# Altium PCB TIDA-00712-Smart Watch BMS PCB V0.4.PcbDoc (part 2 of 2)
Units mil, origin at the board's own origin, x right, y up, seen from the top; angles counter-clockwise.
Board outline 1150 x 800 mil, 2 copper layers (Top Layer, Bottom Layer), stack 11.461 mil thick; 83 components, 53 nets, 288 pads, 152 vias.
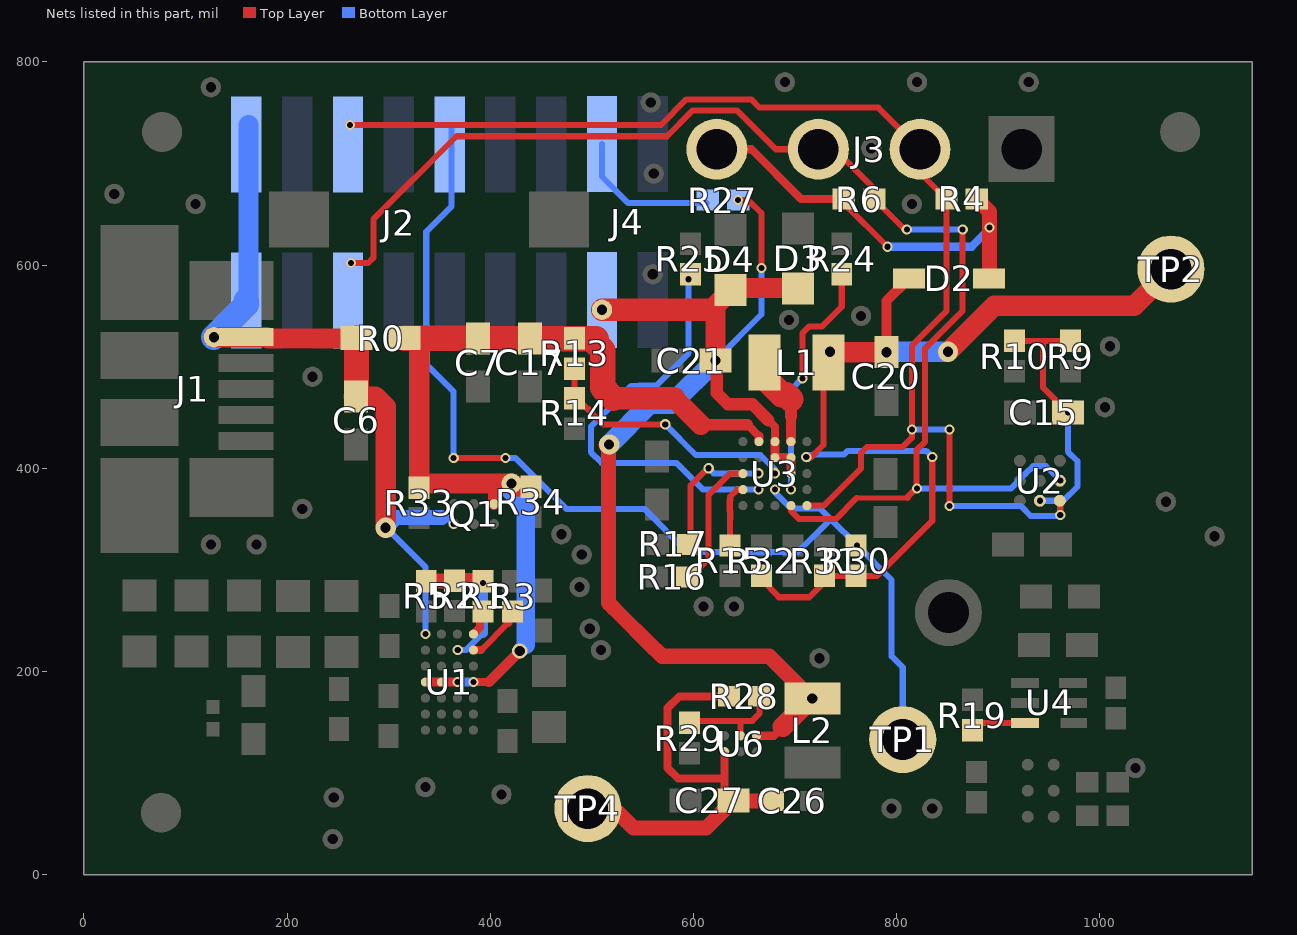
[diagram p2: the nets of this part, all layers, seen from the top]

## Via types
v1: diameter 10, hole 6, Top Layer to Bottom Layer, 77 vias
v2: diameter 20, hole 10, Top Layer to Bottom Layer, 61 vias
v3: diameter 10, hole 6, Top Layer to Bottom Layer, tented bottom, 4 vias
v4: diameter 30, hole 20, Top Layer to Bottom Layer, 4 vias
v5: diameter 16, hole 8, Top Layer to Bottom Layer, tented bottom, 3 vias
v6: diameter 60, hole 40, Top Layer to Bottom Layer, 2 vias
v7: diameter 15, hole 10, Top Layer to Bottom Layer, 1 vias

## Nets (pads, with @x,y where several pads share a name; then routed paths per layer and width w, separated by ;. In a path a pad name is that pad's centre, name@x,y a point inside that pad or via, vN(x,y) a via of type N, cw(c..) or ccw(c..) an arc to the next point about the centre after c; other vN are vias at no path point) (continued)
NetR1_1: R1.1 U1.G1 | length 25
  Top Layer w8: U1.G1@383.37,236.74 390,243.36 R1.1@390,259
NetR1_2: R1.2 R2.2 R5.2 U1.F2 | length 137.5
  Top Layer w6: R1.2@392.5,289.46 R1.2@393,288.96
  Top Layer w15: R5.2@337,288.96 364.26,288.96 R2.2@364.75,289.46 R1.2@392.5,289.46
  Bottom Layer w6: v1(368,221) 376,221 393,238
  Bottom Layer w10: 393,238 v1(393,287)
NetR3_2: R3.2 U1.F1 | length 56.2
  Top Layer w6: 391,221 417.75,247.75
  Top Layer w8: U1.F1@383.37,220.99 391,221 ; 417.75,247.75 R3.2@417.75,258.5
NetR13_1: R13.1 R14.2 U3.C3 | length 260.3
  Top Layer w6: R13.1@483,498.04 R14.2@483,468.96 484.04,470 495.98,458.06 496.55,458.06 501.24,453.38 501.24,452.8 510.79,443.25 v1(572.25,443.25)
  Bottom Layer w6: v1(572.25,443.25) 602.5,413 666,413 680,399 v1(680,395)
NetR15_2: R15.2 U3.D1 | length 64
  Top Layer w6: R15.2@636,323.92 636,350.29 636.18,350.47 636.18,357.32 635.71,357.79 635.71,368.56 636.18,369.03 636.18,372.18 642.92,378.92 U3.D1@648.71,378.92
NetR16_2: R16.2 U3.C1 | length 130.7
  Top Layer w6: R16.2@597,293 615,311 615,374 635.67,394.67 U3.C1@648.71,394.67
NetR17_2: R17.2 U3.C2 | length 136.3
  Top Layer w6: R17.2@593.96,324 R17.2@594.96,325 597,327.04 597,382.92 614.08,400 v1(615,400)
  Bottom Layer w6: v1(615,400) 620,395 v1(664,395)
NetR19_2: R19.2 U4.6 | length 44.5
  Top Layer w6: R19.2@882.08,149.62 882.39,149.32 U4.6@926.46,149.32
NetR24_1: R24.1 U3.D4 | length 240.1
  Top Layer w6: v1(707.25,488.52) 707.25,532.87 713.94,539.56 726.56,539.56 746,559 R24.1@746,591.04
  Bottom Layer w6: v1(696,379) 696,477.27 v1(707.25,488.52)
NetR25_1: R25.1 U3.D2 | length 404.3
  Bottom Layer w6: v1(595,586) 595,512.84 563.41,481.25 546.7,481.25 546.46,481 539,481 499,441 499,415.9 509.54,405.36 583.08,405.36 609.44,379 v1(664,379)
NetR28_1: R28.1 R29.2 U6.B1 | length 104.5
  Top Layer w6: R29.2@596,151.41 646.47,151.41 ; U6.B1@646.47,136.74 646.47,151.41 ; R28.1@661.92,175.49 R28.1@661.92,176.41 ; R28.1@664.96,175.49 664.96,158.45 657.92,151.41 646.47,151.41
PMID: C21.2 D3.1 D4.1 J4.2 L2.1 pad.0@510,556 R27.1 U3.A3 U3.B3 U3.B4 U3.C4 U6.A1 | length 1213.8
  Top Layer w6: v1(643.96,664) 654,664 667,651 v1(667,597)
  Top Layer w8: U6.A1@662.22,136.74 679.25,136.74 688,145.49 ; 674,447 680.2,440.8 U3.A3@680.2,426.17
  Top Layer w9: U3.A3@680.2,426.17 U3.B3@680.2,410.42 U3.B4@695.95,410.42 U3.C4@695.95,394.67
  Top Layer w12: C21.2@623,504 623,474 634,463 658,463 674,447
  Top Layer w15: v2@516.5,422.86 516.5,267.5 521.54,262.46 521.54,262.18 562.22,221.5 562.5,221.5 569,215 674.5,215 L2.1@716,173.49 ; 617.53,556 D4.1@621.62,560.09
  Top Layer w20: v2@516.5,422.86 v2(517,423.36) ; v2(621.62,506) 621.62,560.09 639,577.47 702.53,577.47 D3.1@703,577 ; 688,145.49 L2.1@716,173.49
  Top Layer w22: pad.0@510,556 617.53,556
  Bottom Layer w6: v2(621.62,506) 667,551.38 v1(667,597)
  Bottom Layer w20: v2(517,423.36) 556.89,463.25 578.87,463.25 v2(621.62,506)
  other v2: 717,173.5
PMID-S: J4.1 R27.2 | length 145.8
  Bottom Layer w6: J4.1@510,719 510,687 536,661 R27.2@613.04,661
RESET: J2.9 R30.2 TP1.1 U3.D3 | length 1086.8
  Top Layer w6: v1(364,410) v1(415,410)
  Bottom Layer w6: J2.9@362,737.77 362,657.75 337.04,632.79 337.04,502.31 364,475.35 v1(364,410) ; v1(415,410) 425,410 475,360 551.48,360 594.05,317.43 702.43,317.43 735,350 ; v1(680.2,378.92) 680.2,376.41 696.39,360.22 724.78,360.22 735,350 ; TP1.1@806,133 806,204 795,215 795,290 v1(761,324) 735,350
SCL: J2.5 J3.2 R4.2 U2.A3 U3.E5 | length 1280.9
  Top Layer w6: v1(262,737.77) 567.77,737.77 593,763 657,763 665,755 782,755 J3.2@823,714 823,691.04 R4.2@849.04,665 849.04,554.69 815.35,521 815,521 v1(815,438) 815,430 806,421 771,421 765,415 765,400 728.17,363.17 U3.E5@711.7,363.17 ; v1(852,363) v1(852,438) ; U2.A3@960.68,368 961,368.32 v1(961,354)
  Bottom Layer w6: v1(815,438) v1(852,438) ; v1(852,363) 922,363 932,353 960,353 v1(961,354)
SDA: J2.6 J3.3 R6.2 U2.A2 U3.E4 | length 1321.9
  Top Layer w5: 760.75,370.75 810.75,370.75
  Top Layer w6: v1(263,602) 279.77,602 285,607.23 285,645 366.77,726.77 574,726.77 574,727 599,752 643,752 681,714 J3.3@723,714 ; U3.E4@695.95,363.17 695.95,358.05 704,350 740,350 760.75,370.75 ; J3.3@723,730 777.96,675.04 R6.2@777.96,665 807.96,635 v1(810,635) ; 810.75,370.75 811.25,371.25 ; 810.75,371.75 819.5,380.5 819.5,417.5 828,426 828,518 865,555 v1(865,635)
  Bottom Layer w6: v1(810,635) v1(865,635) ; v1(820,380) 912.09,380 926.46,394.37 926.7,394.37 934.32,401.99 934.32,402.23 946.77,402.23 v1(961,388)
SW: L1.1 U3.A4 | length 91.4
  Top Layer w10: U3.A4@695.95,426.17 695.95,451.05
  Top Layer w12: L1.1@670.01,493.94 L1.1@670.01,504 ; 695.95,451.05 695.95,468
  Top Layer w25: L1.1@670.01,493.94 673.5,490.45 673.5,485.68 686.68,472.5 691.45,472.5 695.95,468
USB_5V: C6.1 J1.1 J2.1 J2.2 pad.0@128,529 Q1.A1 R0.1 U1.G4 | length 766.9
  Top Layer w20: pad.0@128,529 179.76,529 181,527.76 268.13,527.76 R0.1@268.38,528 ; C6.1@268,470.62 286.88,470.62 297,460.5 v2(297,341.48)
  Top Layer w25: C6.1@268,470.62 268.38,471 R0.1@268.38,528
  Bottom Layer w6: v2@297.26,341.74 336.13,302.87 v1(336.13,236.74) ; 355,354 v1(364,345)
  Bottom Layer w15: v2@297.26,341.74 307.15,351.63 352.63,351.63
  Bottom Layer w20: J2.2@160,565 162,567 J2.1@162,737.77
  Bottom Layer w25: pad.0@128,529 160,561 J2.2@160,565
VBOOST: C26.1 C27.1 R28.2 TP4.1 U6.C2 | length 452.2
  Top Layer w6: C27.1@630.72,81.9 C27.1@639.62,73 ; C27.1@633.25,73.49 C27.1@633.72,73.97
  Top Layer w8: C27.1@630.72,81.9 630.72,94.49 ; U6.C2@630.72,120.99 630.72,94.49 ; R28.2@635.04,175.49 586,175.49 574.43,163.92 574.43,105.07 585,94.49 630.72,94.49
  Top Layer w15: TP4.1@483,65 TP4.1@496,65 522,65 541,46 612.62,46 C27.1@639.12,72.49 ; C27.1@639.62,73 C27.1@639.12,72.49 ; C26.1@678.39,72.49 C26.1@677.32,72.49 C27.1@639.12,72.49
VDD: C15.1 R9.1 R10.1 U2.B3 | length 255.3
  Top Layer w6: R10.1@916,525.41 944,525.41 ; v1(968.62,455) 944,479.62 944,525.41 ; R9.1@971,525.41 944,525.41
  Bottom Layer w6: v1(941,368) 964,368 978,382 978,407 968.62,416.38 v1(968.62,455)
VDD_I2C: D2.1 J3.4 R4.1 R6.1 | length 416.4
  Top Layer w6: R6.1@748.04,660.93 v1(791,617.97)
  Top Layer w8: J3.4@623,714 657,714 706,665 R6.1@748.04,665 R6.1@748.04,660.93
  Top Layer w15: R4.1@878.96,665 891.49,652.47 v1(891.49,637) D2.1@891.49,590.4
  Bottom Layer w8: v1(791,617.97) 874.03,617.97 873.9,618.1 v1@892.49,636.69
  Bottom Layer w15: J3.4@609,729 J3.4@626,729
VIN: C7.1 C17.1 Q1.C2 R0.2 R13.2 R33.1 R34.1 U1.D1 U1.D2 U1.D3 U1.D4 U3.A2 | length 1023.2
  Top Layer w8: v3(383.37,189.5) 398.5,189.5 ; 653.08,442.9 664.46,431.53
  Top Layer w9: U1.D4@336.13,189.5 U1.D3@351.88,189.5 v3(367.62,189.5) ; U3.A2@664.46,426.17 664.46,431.53
  Top Layer w10: 398.5,189.5 v7(429,220)
  Top Layer w11: 607.1,442.9 653.08,442.9
  Top Layer w12: Q1.C2@403.68,364.84 403.68,379.68
  Top Layer w15: 333,528.62 C7.1@388,528.62
  Top Layer w20: R33.1@330,380.96 R33.1@330,385 ; 333,528.62 332.38,528 330,525.62 R33.1@330,385 ; v2(421,385) R33.1@330,385 ; v2@424.04,381.96 R34.1@440,381.96 ; 581.2,468.8 607.1,442.9
  Top Layer w22: 521.2,468.8 581.2,468.8
  Top Layer w25: R0.2@315.62,528 332.38,528 387.62,528 C7.1@388,527.62 504.38,527.62 504.38,522.67 510.74,516.31 510.74,479.26 521.2,468.8
  Bottom Layer w9: v3(367.62,189.5) v3(383.37,189.5)
  Bottom Layer w15: v7(429,220) 435,226
  Bottom Layer w18: 435,226 435,363.96
  Bottom Layer w20: v2(421,385) 421,377.96 435,363.96
VSYS: C20.1 D2.2 L1.2 R30.1 R31.1 R32.2 TP2.1 U3.B5 | length 939.1
  Top Layer w6: R32.2@667,294 667,290.6 684,273.6 684,273 714,273 729,288 R31.1@729,294 759.92,294 R30.1@760,294.08 780.83,294.08 835,348.25 v1(835,411) ; v1(711,411) 714.83,411 715.42,410.42 728,423 L1.2@728,489
  Top Layer w10: v2(790,514.24) 790,564.74 D2.2@812.26,587
  Top Layer w20: L1.2@743.24,514.24 v2(790,514.24) ; v2(850.62,514.62) 896,560 1034,560 TP2.1@1070,596
  Top Layer w25: L1.2@733,516 v2(734.38,514.62)
  Bottom Layer w6: v1(711,411) 711.12,411 712.12,410 715.28,413.17 717.09,413.17 717.59,413.67 748.34,413.67 751.68,417 829,417 v1(835,411)
  Bottom Layer w20: v2@790,514.62 v2(850.62,514.62)
pads on no net: FID1.1 FID2.1 FID3.1 J1.2 J1.3 J1.4 J1.6 J1.7 J1.8 J1.9 J1.10 J1.11 Q1.B1 Q1.B2 U1.F4 U4.1

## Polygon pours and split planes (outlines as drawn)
GND on Top Layer "Top Layer-No Net" (solid, remove dead copper, pour order 19): 0,800 1150,800 1150,0 0,0 0,800
GND on Bottom Layer "Top Layer-No Net" (solid, remove dead copper, pour order 23): 0,800 1150,800 1150,0 0,0 -2.09,2.09 -2.09,800

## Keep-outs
Keep-Out Layer:
  lines w5: 0,0 0,800 1150,800 1150,0 0,0
  lines w10: -5,3450 cw(c0,3450) 0,3455 ccw(c0,3450) -5,3450 ; 4950,3455 cw(c4950,3450) 4955,3450 ccw(c4950,3450) 4950,3455
  text ".Layer_Name" at 577,-858.49 h44

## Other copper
Top Layer:
  text ".Layer_Name" at 577,-858.49 h44
Bottom Layer:
  text ".Layer_Name" at 577,-858.49 h44

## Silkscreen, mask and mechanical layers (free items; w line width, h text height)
Top Overlay:
  text ".Layer_Name" at 577,-858.49 h40
Bottom Overlay:
  lines w4: 35.14,66 35.14,146 ; 75.14,92.67 35.14,106 ; 75.14,119.33 35.14,106 ; 214.27,106 35.14,106 ; 297,106 476.14,106 ; 376.53,117.99 456.53,117.99 ; 376.53,301.99 456.53,301.99 ; 403.2,157.99 416.53,117.99 ; 403.2,261.99 416.53,301.99 ; 416.53,167.94 416.53,117.99 ; 416.53,252.04 416.53,301.99 ; 429.86,157.99 416.53,117.99 ; 429.86,261.99 416.53,301.99 ; 436.14,92.67 476.14,106 ; 436.14,119.33 476.14,106 ; 476.14,66 476.14,146 ; 547.18,440 547.18,520 ; 562,280 642,280 ; 562,537 642,537 ; 587.18,466.67 547.18,480 ; 587.18,493.33 547.18,480 ; 588.67,320 602,280 ; 588.67,497 602,537 ; 589,91.67 589,99.67 ; 602,341.18 602,280 ; 602,475.82 602,537 ; 609.37,480 547.18,480 ; 615.33,320 602,280 ; 615.33,497 602,537 ; 629,82.33 589,95.67 ; 629,109 589,95.67 ; 640.4,95.67 589,95.67 ; 724.6,95.67 776,95.67 ; 736,82.33 776,95.67 ; 736,109 776,95.67 ; 744,480 806.18,480 ; 766.18,466.67 806.18,480 ; 766.18,493.33 806.18,480 ; 776,91.67 776,99.67 ; 806.18,440 806.18,520 ; 843,216 843,224 ; 883,206.67 843,220 ; 883,233.33 843,220 ; 885.38,220 843,220 ; 944.33,82.59 957.67,42.59 ; 944.33,198.59 957.67,238.59 ; 953.67,42.59 961.67,42.59 ; 953.67,238.59 961.67,238.59 ; 957.67,98.49 957.67,42.59 ; 957.67,182.69 957.67,238.59 ; 969.62,220 1012,220 ; 971,82.59 957.67,42.59 ; 971,198.59 957.67,238.59 ; 972,206.67 1012,220 ; 972,233.33 1012,220 ; 1012,216 1012,224
  lines w5: 35,119 35,303 476,303 476,119 35,119 ; 547,279.5 547,537 806,537 806,279.5 547,279.5 ; 589,69 589,211 777,211 777,69 589,69 ; 843,44 843,241 1012,241 1012,44 843,44 ; 902,359 902,470 987,470 987,359 902,359
  text "BQ25120" at 808.15,569.32 h40
  text "V0.3" at 43,514 h40 r270
  text "BQ27421" at 1045,476 h40
  text "259" at 619.37,456.01 h40
  text "TIDA-00712" at 382,438 h40
  text "257" at 625.99,351.18 h40 r90
  text "BQ51003" at 266,335 h40
  text "BQ29702" at 1133,285 h40
  text "Bster" at 712,220 h40
  text "169" at 895.38,201.92 h40
  text "184" at 434.61,177.94 h40 r90
  text "196" at 975.75,108.49 h40 r90
  text "441" at 224.27,88.14 h40
  text "187" at 650.4,77.59 h40
  text ".Layer_Name" at 577,-858.49 h44
Top Paste:
  text ".Layer_Name" at 577,-858.49 h44
Bottom Paste:
  text ".Layer_Name" at 577,-858.49 h44
Top Solder:
  text ".Layer_Name" at 577,-858.49 h44
  text ".Layer_Name" at 577,-858.49 h44
Bottom Solder:
  text ".Layer_Name" at 577,-858.49 h44
Drill Guide:
  text ".Layer_Name" at 577,-858.49 h44
M1 Board Outline:
  the board outline again, w5
  text ".Layer_Name" at 577,-858.49 h44
M2 Board Dimensions:
  rectangle: 0,-275 125,-150
  rectangle: 125,-400 500,-275
  lines w5: 0,0 0,800 1150,800 1150,0 0,0
  lines w7: 0,-275 1000,-275 ; 125,-400 125,-150 ; 250,-400 250,-150 ; 500,-400 500,-150 ; 750,-400 750,-150 ; 0,-400 1000,-400 1000,-150 0,-150 0,-400
  lines w10: -72.8,750.04 -56.83,800.27 ; -66.83,800.13 -46.83,800.41 ; -63.18,50.04 -45.83,0.27 ; -55.83,0.13 -35.83,0.41 ; -55.53,705.81 -56.83,800.27 ; -47.13,94.73 -45.83,0.27 ; -39.47,750.5 -56.83,800.27 ; -29.85,50.49 -45.83,0.27 ; -0.05,-53.1 -0.02,-33.1 ; 49.94,-59.86 -0.03,-43.1 ; 49.99,-26.52 -0.03,-43.1 ; 252.73,-43.54 -0.03,-43.1 ; 897.2,-44.66 1149.97,-45.1 ; 1099.94,-61.68 1149.97,-45.1 ; 1099.99,-28.35 1149.97,-45.1 ; 1149.95,-55.1 1149.98,-35.1
  text "800.076 (mil)" at -84.38,695.42 h50 r270.79
  text "1150.002 (mil)" at 262.68,-72.55 h50 r359.9
  text ".Layer_Name" at 577,-858.49 h44
M3 3D STEP Top:
  text ".Layer_Name" at 577,-858.49 h44
M4 3D STEP Bottom:
  text ".Layer_Name" at 577,-858.49 h44
M5 Assembly Top:
  lines w10: -292,-930.17 6308,-930.17 ; -292,-726.83 6310,-726.83 ; -292,-523.5 -292,-1133.5 3713,-1133.5 6310,-1133.5 6310,-523.5 -291.5,-523.5 -291.5,-1133.5 1284,-1133.5 ; 2173,-1133.5 2173,-523.5 ; 3440,-726.83 3440,-523.5 ; 4280,-726.83 4280,-523.5 ; 4902,-1140 4902,-937.17
  text "COMPONENTS MARKED 'DNP' SHOULD NOT BE POPULATED." at 1153.5,-318.5 h44
  text "ASSEMBLY VARIANT:" at 1153,-434 h44
  text ".VariantName" at 2189,-434 h44
  text "PCB VIEWED FROM TOP SIDE" at -228.5,-655.67 h44
  text "BOARD #:" at 2248,-655.67 h44
  text ".PRJ_Number" at 2793.5,-655.67 h44
  text "REV:" at 3638,-655.67 h44
  text ".PCB_Rev" at 3929.5,-655.67 h44
  text "SVN REV:" at 4476,-655.67 h44
  text ".VersionControl_RevNumber" at 4982,-655.67 h44
  text "TID #:" at 2248,-859 h44
  text ".TID" at 2793.5,-859 h44
  text "PLOT NAME =" at -228.5,-1064.34 h44
  text ".plot_File_Name" at 577,-1064.34 h44
  text "GENERATED    :" at 2250,-1064.34 h44
  text ".Print_Date" at 3119.5,-1064.34 h44
  text ".Print_Time" at 3848.5,-1064.34 h44
  text "TEXAS INSTRUMENTS" at 5113,-1064.34 h44
M6 Assembly Bottom:
  lines w10: -292.5,-727.33 6309.5,-727.33 ; -290.5,-930.67 6309.5,-930.67 ; 1115.5,-1140.5 1115.5,-937.67 ; 1737.5,-727.33 1737.5,-524 ; 2577.5,-727.33 2577.5,-524 ; 3844.5,-1134 3844.5,-524 ; 4733.5,-1134 6309,-1134 6309,-524 -292.5,-524 -292.5,-1134 2304.5,-1134 6309.5,-1134 6309.5,-524
  text "COMPONENTS MARKED 'DNP' SHOULD NOT BE POPULATED." at 6102,-318 h44
  text ".VariantName" at 5058,-434 h44
  text "ASSEMBLY VARIANT:" at 6097,-434 h44
  text ".VersionControl_RevNumber" at 1035.5,-656.17 h44
  text "SVN REV:" at 1541.5,-656.17 h44
  text ".PCB_Rev" at 2088,-656.17 h44
  text "REV:" at 2379.5,-656.17 h44
  text ".PRJ_Number" at 3224,-656.17 h44
  text "BOARD #:" at 3769.5,-656.17 h44
  text "PCB VIEWED FROM BOTTOM SIDE" at 6246,-656.17 h44
  text ".TID" at 3224,-859.5 h44
  text "TID #:" at 3769.5,-859.5 h44
  text "TEXAS INSTRUMENTS" at 904.5,-1064.84 h44
  text ".Print_Time" at 2169,-1064.84 h44
  text ".Print_Date" at 2898,-1064.84 h44
  text "GENERATED    :" at 3767.5,-1064.84 h44
  text ".plot_File_Name" at 5440.5,-1064.84 h44
  text "PLOT NAME =" at 6246,-1064.84 h44
M9 Title Sheet:
  drawing of 57 lines, arcs and shapes, not listed
  text "1" at 739.84,8036.5 h44
  text "2" at 3235.5,8036.5 h44
  text "3" at 5724.84,8036.5 h44
  text "4" at 8231.51,8036.5 h44
  text "5" at 10730.5,8036.5 h44
  text "6" at 13235.5,8036.5 h44
  text "A" at -416.5,6893.5 h44
  text "A" at 14383.5,6893.5 h44
  text "B" at -416.5,4513.5 h44
  text "B" at 14383.5,4513.5 h44
  text "C" at -416.5,2138.5 h44
  text "C" at 14383.5,2138.5 h44
  text "PROJECT TITLE:" at 11343.5,277.5 h44
  text ".PRJ_Title" at 11393.5,144.17 h44
  text "DESIGNED FOR:" at 11343.5,-23.5 h44
  text ".PRJ_Customer" at 11393.5,-163.5 h44
  text "D" at -416.5,-231.5 h44
  text "D" at 14383.5,-231.5 h44
  text "FILE NAME:" at 11343.5,-323.5 h44
  text ".PCB_File_Name_No_Path" at 11393.5,-443.5 h44
  text "Texas Instruments (TI) and/or its licensors do not warrant the accuracy or completeness of this specification" at 6374,-605.34 h44
  text "ENGINEER:" at 11343.5,-613.5 h44
  text "LAYOUT BY:" at 12848.5,-613.5 h44
  text "or any information contained therein. TI and/or its licensors do not warrant that this design will meet" at 6329.01,-718 h44
  text ".PRJ_Engineer" at 11393.5,-768.49 h44
  text ".PCB_Layout" at 12899,-768.49 h44
  text "the specifications, will be suitable for your application or fit for any particular purpose, or will operate in" at 6329.01,-830.67 h44
  text ".Layer_Name" at 577,-858.49 h44
  text "ALTIUM DESIGNER VERSION:" at 12848.5,-923.5 h44
  text "an implementation. TI and/or its licensors do not warrant that the design is production worthy. You should" at 6329.01,-943.33 h44
  text "completely validate and test your design implementation to confirm the system functionality for your application." at 6374,-1056 h44
  text ".print_Scale" at 11393.5,-1056.83 h44
  text ".Application_BuildNumber" at 12899,-1056.83 h44
  text "1" at 739.84,-1263.5 h44
  text "2" at 3235.5,-1263.5 h44
  text "3" at 5724.84,-1263.5 h44
  text "4" at 8231.51,-1263.5 h44
  text "5" at 10730.5,-1263.5 h44
  text "6" at 13235.5,-1263.5 h44
M10 Fab Notes:
  drawing of 185 lines, arcs and shapes, not listed
  text "DESIGN INFORMATION" at 12381.02,5910 h44
  text "MIN. TRACK WIDTH:" at 11736.46,5730 h44
  text "8" at 12832.7,5730 h44
  text "MIL" at 12987.46,5730 h44
  text "MIN. CLEARANCE:" at 11736.46,5598 h44
  text "0.2" at 12772.7,5598 h44
  text "mm" at 12987.46,5598 h44
  text "MIN. VIA PAD SIZE:" at 11736.46,5466 h44
  text "24" at 12802.71,5466 h44
  text "MIL" at 12987.46,5466 h44
  text "0.05mm (2MIL)" at 12431.46,5324.29 h44
  text "MINIMUM ANNULAR RING" at 11407.23,5320 h44
  text "EXTERNAL" at 13139.46,5320 h44
  text "PER" at 11607.23,5202 h44
  text "IPC-D-275 CLASS 2 LEVEL C" at 11827.23,5202 h44
  text "MIL, HOLES" at 13315.46,5089.71 h44
  text "+/-" at 12923,5089 h44
  text "+/-" at 13777,5089 h44
  text "REGISTRATION TOLERANCES:" at 11407.23,5084 h44
  text "METAL" at 12607,5084 h44
  text "5" at 13183.2,5084 h44
  text "3" at 14016.2,5084 h44
  text "MIL" at 14132.46,5084 h44
  text "MATERIAL:" at 11332.46,4874.54 h44
  text "FR-4 High Tg" at 12318.9,4734.21 h44
  text "FR-408" at 11753.46,4725.64 h44
  text "X" at 12165.46,4725.64 h44
  text "OTHER" at 13241.46,4725.64 h44
  text "62 MIL (1.6mm) +/-10%" at 12073.56,4562.92 h44
  text "THICKNESS:" at 11407.23,4558.64 h44
  text "X" at 11945.4,4558.64 h44
  text "OTHER" at 13358.46,4558.64 h44
  text "TOLERANCE:" at 11407.23,4400.64 h44
  text "X" at 12246.53,4400.64 h44
  text "ANSI IPC-6012 TYPE 3 CLASS 2" at 12433.48,4400.64 h44
  text "OTHER +/-" at 12433.46,4244.64 h44
  text "BOW & TWIST:" at 11407.23,4087.64 h44
  text "X" at 12246.53,4087.64 h44
  text "ANSI IPC-6012 TYPE 3 CLASS 2" at 12433.48,4087.64 h44
  text "OTHER +/-" at 12433.46,3929.13 h44
  text "DRILLING:" at 11332.46,3790.64 h44
  text "REFERENCE:" at 11407.23,3673.64 h44
  text "X" at 12055.46,3673.64 h44
  text "AS SHOWN" at 12242.46,3673.64 h44
  text "X" at 12956.46,3673.64 h44
  text "NC_DRILL FILES" at 13093.46,3673.64 h44
  text "PTH MIN COPPER THICKNESS:" at 11407.23,3515.64 h44
  text "X" at 12757.46,3515.64 h44
  text "1MIL" at 12894.46,3515.64 h44
  text "OTHER" at 13391.46,3515.64 h44
  text "BOARD FINISH:" at 11332.46,3356.64 h44
  text "SILKSCREEN:" at 11487.68,3238.64 h44
  text "X" at 12436.46,3238.64 h44
  text "TOP" at 12562.46,3238.64 h44
  text "X" at 12946.46,3238.64 h44
  text "BOTTOM" at 13073.46,3238.64 h44
  text "SILKSCREEN COLOR:" at 11487.68,3071.64 h44
  text "X" at 12435.42,3071.64 h44
  text "WHITE" at 12562.46,3071.64 h44
  text "OTHER" at 13073.46,3071.64 h44
  text "SOLDER RESIST COLOR:" at 11487.68,2901.64 h44
  text "X" at 12055.42,2742.44 h44
  text "GREEN" at 12182.46,2742.44 h44
  text "BLUE" at 12773.46,2742.44 h44
  text "OTHER" at 13311.46,2742.44 h44
  text "IMMERSION GOLD (ENIG)" at 12393.46,2553.92 h44
  text "ENEPIG" at 13731,2550.64 h44
  text "SURFACE FINISH:" at 11332.46,2549.64 h44
  text "X" at 12206.51,2549.64 h44
  text "IMM. TIN/SILVER OR EQUIV" at 11662,2392.64 h44
  text "OTHER" at 13093.46,2392.64 h44
  text "ARRAY/PANEL:" at 11332.46,2213.64 h44
  text "CUT AND TRIM PER MECH LAYER 1" at 12393.46,2209.35 h44
  text "N.C. ROUTE" at 12393.46,2057.64 h44
  text "X" at 13072.46,2057.64 h44
  text "V. SCORE" at 13259.46,2057.64 h44
  text "CERTIFICATION:" at 11332.46,1920.64 h44
  text "MATERIALS AND WORKMANSHIP FOR ALL PCBS" at 12057.46,1920.64 h44
  text "TO MEET OR EXCEED THE REQUIREMENTS OF:" at 12057.46,1822.64 h44
  text "X" at 5613.96,1676.13 h44
  text "ANSI IPC-A-600F CLASS ->" at 5752.96,1676.13 h44
  text "X" at 7392.02,1676.13 h44
  text "2" at 7510.96,1676.14 h44
  text "1" at 7195.96,1674.64 h44
  text "3" at 7864.96,1674.64 h44
  text "X" at 5616.02,1516.64 h44
  text "UL 94V-0" at 5752.96,1516.64 h44
  text "X" at 6428.02,1516.64 h44
  text "RoHS" at 6564.96,1516.64 h44
  text "OTHER" at 7209.36,1516.64 h44
  text "PER ORDER" at 7606.42,1516.64 h44
  text "ADDITIONAL REQUIREMENTS:" at 5262.46,1375.64 h44
  text "MICROSECTION:" at 5337.23,1260.64 h44
  text "YES" at 6242.96,1260.64 h44
  text "REQUIRED" at 7104.46,1104.49 h44
  text "BARE BOARD ELEC. TEST:" at 5337.23,1101.64 h44
  text "NONE" at 6642.96,1101.64 h44
  text "X" at 6977.46,1101.64 h44
  text "PER ORDER" at 7696.46,1101.64 h44
  text "MANUFACTURER'S UL:" at 5337.23,944.64 h44
  text "RAIL" at 6502.96,940.35 h44
  text "METAL" at 6994.77,940.35 h44
  text "X" at 7370,940 h44
  text "SILK" at 7506.46,940.35 h44
  text ".Layer_Name" at 577,-858.49 h44
M11 Gerber Information:
  lines w10: -292,-930.17 6308,-930.17 ; -292,-726.83 6310,-726.83 ; -292,-523.5 -292,-1133.5 3713,-1133.5 6310,-1133.5 6310,-523.5 -291.5,-523.5 -291.5,-1133.5 1284,-1133.5 ; 2173,-1133.5 2173,-523.5 ; 3440,-726.83 3440,-523.5 ; 4280,-726.83 4280,-523.5 ; 4902,-1140 4902,-937.17
  text "ALL ARTWORK VIEWED FROM TOP SIDE" at -228.5,-655.67 h44
  text "BOARD #:" at 2248,-655.67 h44
  text ".PRJ_Number" at 2793.5,-655.67 h44
  text "REV:" at 3638,-655.67 h44
  text ".PCB_Rev" at 3929.5,-655.67 h44
  text "SVN REV:" at 4476,-655.67 h44
  text ".VersionControl_RevNumber" at 4982,-655.67 h44
  text "LAYER NAME =" at -228.5,-858.49 h44
  text "TID #:" at 2248,-859 h44
  text ".TID" at 2793.5,-859 h44
  text "PLOT NAME =" at -228.5,-1064.34 h44
  text ".plot_File_Name" at 577,-1064.34 h44
  text "GENERATED    :" at 2250,-1064.34 h44
  text ".Print_Date" at 3119.5,-1064.34 h44
  text ".Print_Time" at 3848.5,-1064.34 h44
  text "TEXAS INSTRUMENTS" at 5113,-1064.34 h44
M12 Stackup:
  drawing of 295 lines, arcs and shapes, not listed
  text "Layer" at 9774.58,7862 h44
  text "Name" at 10068.51,7862 h44
  text "Material" at 10824.3,7862 h44
  text "Thickness" at 11448.13,7862 h44
  text "Constant" at 11918.01,7862 h44
  text "Board Layer Stack" at 12329.24,7862 h44
  text "1" at 9774.58,7774 h44
  text "Top Overlay" at 10068.51,7774 h44
  text "2" at 9774.58,7686 h44
  text "Top Solder" at 10068.51,7686 h44
  text "Solder Resist" at 10824.3,7686 h44
  text "0.40mil" at 11448.13,7686 h44
  text "3.5" at 11918.01,7686 h44
  text "3" at 9774.58,7598 h44
  text "Top Layer" at 10068.51,7598 h44
  text "Copper" at 10824.3,7598 h44
  text "1.40mil" at 11448.13,7598 h44
  text "4" at 9774.58,7510 h44
  text "Dielectric1" at 10068.51,7510 h44
  text "FR-4" at 10824.3,7510 h44
  text "59.20mil" at 11448.13,7510 h44
  text "4.8" at 11918.01,7510 h44
  text "5" at 9774.58,7422 h44
  text "Internal Plane 1" at 10068.51,7422 h44
  text "Copper" at 10824.3,7422 h44
  text "1.42mil" at 11448.13,7422 h44
  text "6" at 9774.58,7334 h44
  text "Dielectric 3" at 10068.51,7334 h44
  text "5.00mil" at 11448.13,7334 h44
  text "4.2" at 11918.01,7334 h44
  text "7" at 9774.58,7246 h44
  text "Internal Plane 2" at 10068.51,7246 h44
  text "Copper" at 10824.3,7246 h44
  text "1.42mil" at 11448.13,7246 h44
  text "8" at 9774.58,7158 h44
  text "Dielectric 2" at 10068.51,7158 h44
  text "10.00mil" at 11448.13,7158 h44
  text "4.2" at 11918.01,7158 h44
  text "9" at 9774.58,7070 h44
  text "Bottom Layer" at 10068.51,7070 h44
  text "Copper" at 10824.3,7070 h44
  text "1.40mil" at 11448.13,7070 h44
  text "10" at 9774.58,6982 h44
  text "Bottom Solder" at 10068.51,6982 h44
  text "Solder Resist" at 10824.3,6982 h44
  text "0.40mil" at 11448.13,6982 h44
  text "3.5" at 11918.01,6982 h44
  text "11" at 9774.58,6894 h44
  text "Bottom Overlay" at 10068.51,6894 h44
  text ".Layer_Name" at 577,-858.49 h44
M13 Component Bodies Top:
  text ".Layer_Name" at 577,-858.49 h44
M14 Component Bodies Bottom:
  text ".Layer_Name" at 577,-858.49 h44
M15 Courtyards Top:
  text ".Layer_Name" at 577,-858.49 h44
M16 Courtyards Bottom:
  text ".Layer_Name" at 577,-858.49 h44
Drill Drawing:
  circle w1: c5552.83,2923.37 r11.62
  circle w1: c5552.83,2923.37 r19.36
  lines w1: 5533.46,2826.56 5572.19,2826.56 5552.83,2787.84 5533.46,2826.56 ; 5533.46,3020.18 5572.19,3020.18 5572.19,3058.9 5533.46,3058.9 5533.46,3020.18 ; 5533.46,3136.35 5572.19,3136.35 5572.19,3175.07 5533.46,3175.07 5533.46,3136.35 ; 5533.46,3271.88 5552.83,3252.51 5572.19,3271.88 5552.83,3291.24 5533.46,3271.88 ; 5541.21,3027.92 5564.44,3027.92 5564.44,3051.16 5541.21,3051.16 5541.21,3027.92
  lines w12: 5480,2752.99 7069.63,2752.99 ; 5480,3333.83 7069.63,3333.83 ; 5760.13,2636.82 5760.13,3450 ; 6028.44,2636.82 6028.44,3450 ; 6519.92,2636.82 6519.92,3450 ; 6734.84,2636.82 6734.84,3450 ; 5480,2636.82 7069.63,2636.82 7069.63,3450 5480,3450 5480,2636.82
  text "Symbol" at 5549.7,3368.68 h52.8
  text "Quantity" at 5794.98,3368.68 h52.8
  text "Finished Hole Size" at 6063.29,3368.68 h52.8
  text "Plated" at 6554.77,3368.68 h52.8
  text "Hole Type" at 6769.69,3368.68 h52.8
  text "81" at 5794.98,3252.51 h44
  text "6.00mil (0.152mm)" at 6063.29,3252.51 h44
  text "PTH" at 6554.77,3252.51 h44
  text "Round" at 6769.69,3252.51 h44
  text "3" at 5794.98,3136.35 h44
  text "8.00mil (0.203mm)" at 6063.29,3136.35 h44
  text "PTH" at 6554.77,3136.35 h44
  text "Round" at 6769.69,3136.35 h44
  text "100" at 5794.98,3020.18 h44
  text "10.00mil (0.254mm)" at 6063.29,3020.18 h44
  text "PTH" at 6554.77,3020.18 h44
  text "Round" at 6769.69,3020.18 h44
  text "4" at 5794.98,2904.01 h44
  text "20.00mil (0.508mm)" at 6063.29,2904.01 h44
  text "PTH" at 6554.77,2904.01 h44
  text "Round" at 6769.69,2904.01 h44
  text "10" at 5794.98,2787.84 h44
  text "40.00mil (1.016mm)" at 6063.29,2787.84 h44
  text "PTH" at 6554.77,2787.84 h44
  text "Round" at 6769.69,2787.84 h44
  text "198 Total" at 5794.98,2671.67 h44
  text ".Layer_Name" at 577,-858.49 h44

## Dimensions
0,-400 to 1000,-400 on M2 Board Dimensions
